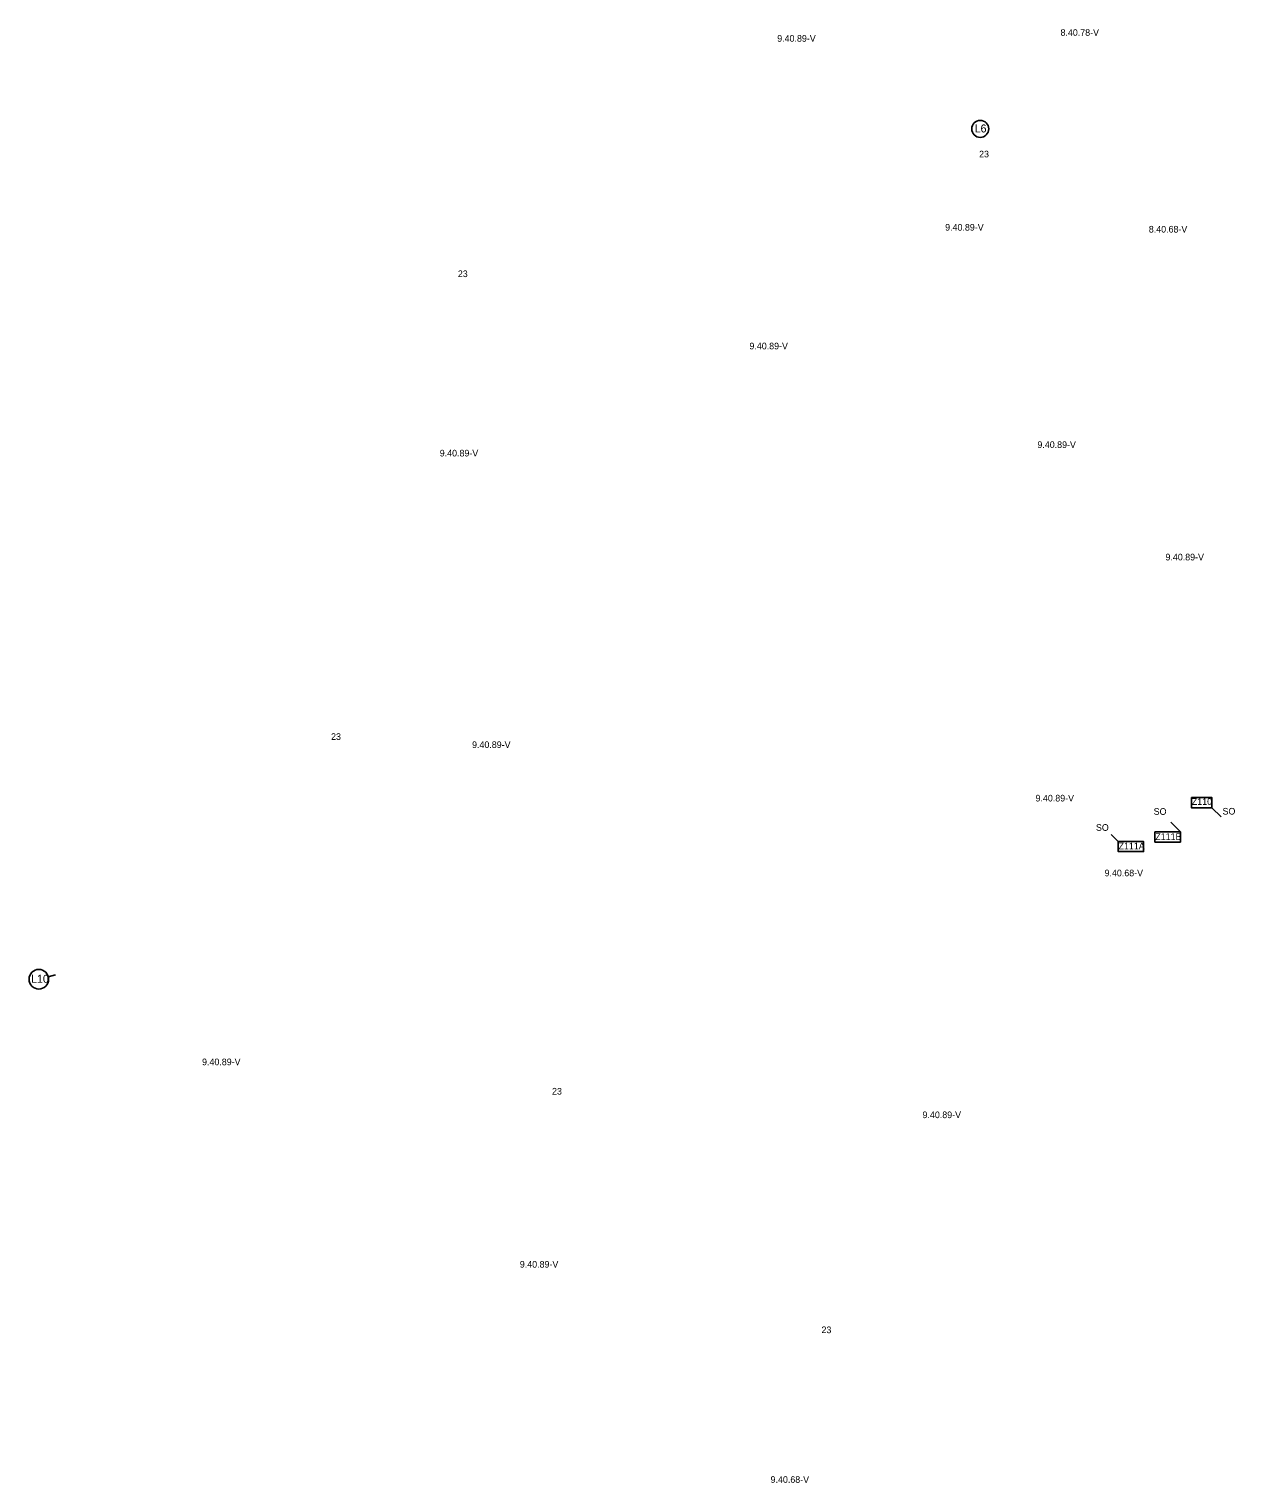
# Model space of a CAD drawing. Extents: x -450307 to -440553, y -1134449 to -1129789.
# Drawn here: x -445081 to -443263, y -1134449 to -1132259 of the extents above; entities that cross this region are included whole.
import ezdxf

# ---------------------------------------------------------------- set-up
doc = ezdxf.new("R2010")
doc.units = 0
for name, color, linetype in [('Vrstva 18', 7, 'Continuous'), ('Vrstva 28', 7, 'Continuous'), ('Vrstva 36', 7, 'Continuous')]:
    doc.layers.add(name, color=color, linetype=linetype)

msp = doc.modelspace()

# ---------------------------------------------------------------- linework, layer by layer
at = {"layer": 'Vrstva 18'}
for p, q in [((-443283.8, -1133446.1), (-443298, -1133432.4)), ((-443345.5, -1133468.6), (-443359.7, -1133454.2)), ((-443439.2, -1133483.2), (-443449.7, -1133472.6))]:
    msp.add_line(p, q, dxfattribs=at)
for points in [[(-443328.8, -1133417), (-443298, -1133417), (-443298, -1133432.4), (-443328.8, -1133432.4)], [(-443439.2, -1133483.2), (-443400.8, -1133483.2), (-443400.8, -1133498.5), (-443439.2, -1133498.5)], [(-443383.9, -1133468.6), (-443345.5, -1133468.6), (-443345.5, -1133484), (-443383.9, -1133484)]]:
    msp.add_lwpolyline(points, close=True, dxfattribs=at)
at = {"layer": 'Vrstva 36'}
msp.add_line((-445051.5, -1133686.8), (-445040.8, -1133683.9), dxfattribs=at)
for centre, radius in [((-443647, -1132409.8), 12.8), ((-445065.8, -1133690.7), 14.8)]:
    msp.add_circle(centre, radius, dxfattribs=at)

# ---------------------------------------------------------------- texts
at = {"layer": 'Vrstva 18'}
for s, p in [('Z110', (-443328.2, -1133428)), ('SO', (-443385.7, -1133443)), ('SO', (-443281.9, -1133442.6)), ('SO', (-443472.7, -1133467.1)), ('Z111A', (-443438.6, -1133494.9)), ('Z111B', (-443383.2, -1133480.8))]:
    msp.add_text(s, height=10, dxfattribs=at).set_placement(p)
at = {"layer": 'Vrstva 28'}
for s, p in [('8.40.78-V', (-443526.1, -1132269.6)), ('9.40.89-V', (-443953, -1132278.5)), ('23', (-443648.8, -1132452.7)), ('9.40.89-V', (-443699.9, -1132563)), ('8.40.68-V', (-443393, -1132565.9)), ('23', (-444434.3, -1132633)), ('9.40.89-V', (-443994.9, -1132741.8)), ('9.40.89-V', (-444461.6, -1132903.2)), ('9.40.89-V', (-443560.9, -1132890.4)), ('9.40.89-V', (-443367.9, -1133059.8)), ('23', (-444625.4, -1133330.1)), ('9.40.89-V', (-444412.9, -1133342.4)), ('9.40.89-V', (-443563.7, -1133422.9)), ('9.40.68-V', (-443459.7, -1133535.6)), ('9.40.89-V', (-444819.8, -1133820.2)), ('23', (-444292.4, -1133864.4)), ('9.40.89-V', (-443734, -1133899.9)), ('9.40.89-V', (-444340.9, -1134125.1)), ('23', (-443886.3, -1134223.8)), ('9.40.68-V', (-443963, -1134449.3))]:
    msp.add_text(s, height=10, dxfattribs=at).set_placement(p)
at = {"layer": 'Vrstva 36'}
for s, p in [('L6', (-443655.5, -1132415.1)), ('L10', (-445077.5, -1133696))]:
    msp.add_text(s, height=12, dxfattribs=at).set_placement(p)

doc.saveas('drawing.dxf')
